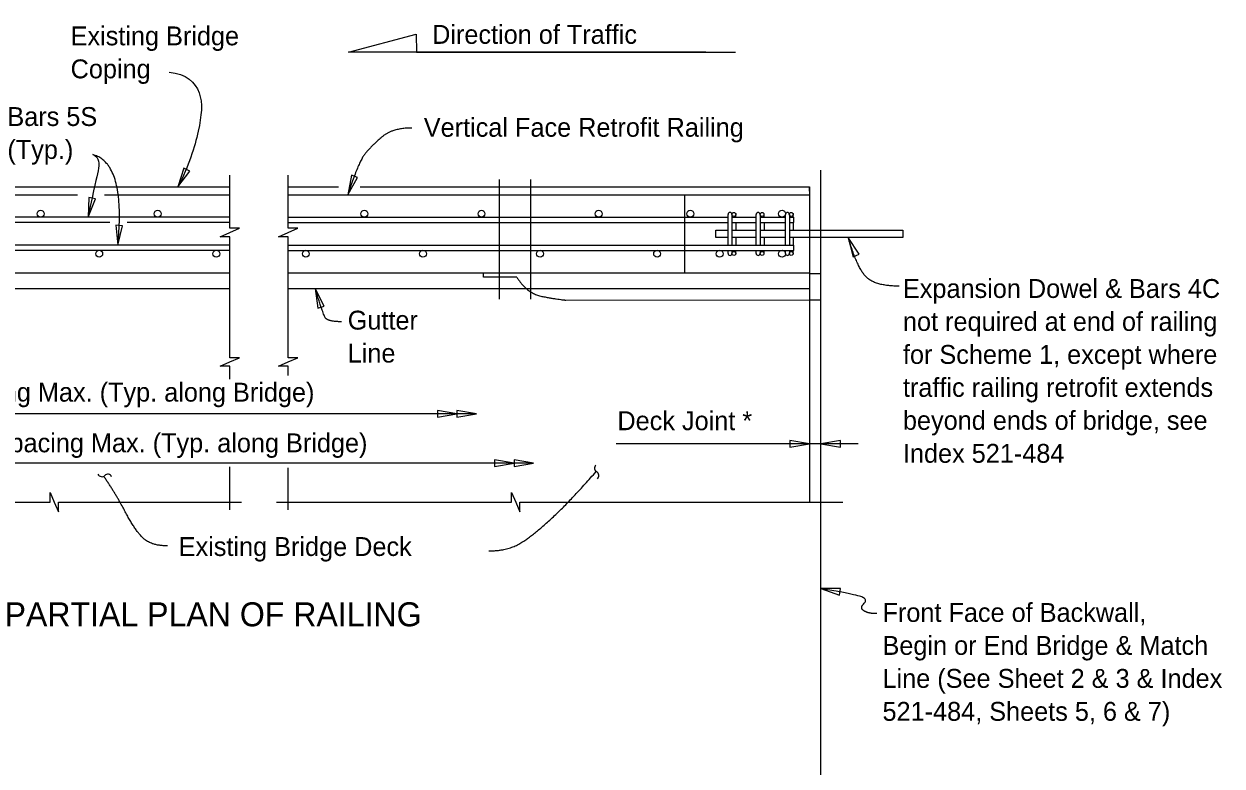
# Model space of a CAD drawing. Extents: x 0.1 to 40.1, y 0.1 to 25.4.
# Drawn here: x 6.61 to 19.4, y 17.39 to 25.31 of the extents above; entities that cross this region are included whole.
import ezdxf

# ---------------------------------------------------------------- set-up
doc = ezdxf.new("R2010")
doc.units = 0
for name, color, linetype in [('Dimension', 7, 'Continuous'), ('Miscellaneous', 7, 'Continuous'), ('Rebar', 7, 'Continuous'), ('TextStructures', 7, 'Continuous'), ('TrafBarrierConc', 7, 'Continuous')]:
    doc.layers.add(name, color=color, linetype=linetype)

msp = doc.modelspace()

# ---------------------------------------------------------------- linework, layer by layer
at = {"layer": 'Dimension'}
for p, q in [((10.079, 25.008), (10.801, 25.2)), ((10.801, 25.2), (10.803, 25.008)), ((13.892, 25.008), (10.079, 25.008)), ((10.803, 25.008), (14.016, 25.008)), ((14.016, 25.008), (14.209, 25.008)), ((15.121, 9.931), (15.121, 23.75)), ((11.687, 23.649), (11.687, 22.373)), ((12.021, 23.649), (12.021, 22.373)), ((11.444, 21.148), (3.78, 21.148)), ((15.518, 20.828), (12.934, 20.828)), ((12.054, 20.62), (3.78, 20.62))]:
    msp.add_line(p, q, dxfattribs=at)
for points in [[(8.257, 23.57), (8.385, 23.739), (8.322, 23.771)], [(10.071, 23.487), (10.175, 23.671), (10.109, 23.695)], [(7.299, 23.247), (7.376, 23.444), (7.306, 23.458)], [(7.616, 22.95), (7.666, 23.155), (7.596, 23.161)], [(15.412, 23.03), (15.466, 22.825), (15.53, 22.854)], [(9.723, 22.484), (9.751, 22.275), (9.818, 22.296)], [(11.236, 21.148), (11.027, 21.183), (11.027, 21.113)], [(11.444, 21.148), (11.236, 21.183), (11.236, 21.113)], [(14.998, 20.828), (14.79, 20.864), (14.79, 20.793)], [(15.121, 20.828), (15.329, 20.793), (15.329, 20.864)], [(11.846, 20.62), (11.638, 20.656), (11.638, 20.585)], [(12.054, 20.62), (11.846, 20.656), (11.846, 20.585)], [(15.119, 19.281), (15.319, 19.212), (15.33, 19.282)]]:
    msp.add_lwpolyline(points, close=True, dxfattribs=at)
for points in [[(8.81, 22.036), (8.81, 23.039), (8.707, 23.039), (8.81, 23.084), (8.913, 23.129), (8.81, 23.129), (8.81, 23.695)], [(9.435, 22.036), (9.435, 23.039), (9.332, 23.039), (9.435, 23.084), (9.539, 23.129), (9.435, 23.129), (9.435, 23.695)], [(8.81, 21.518), (8.81, 21.656), (8.707, 21.656), (8.81, 21.701), (8.913, 21.746), (8.81, 21.746), (8.81, 22.036)], [(9.435, 21.558), (9.435, 21.656), (9.332, 21.656), (9.435, 21.701), (9.539, 21.746), (9.435, 21.746), (9.435, 22.036)], [(8.81, 20.123), (8.81, 20.58)], [(9.435, 20.123), (9.435, 20.57)], [(5.406, 20.203), (6.892, 20.203), (6.892, 20.306), (6.937, 20.203), (6.982, 20.1), (6.982, 20.203), (8.935, 20.203)], [(9.31, 20.203), (11.818, 20.203), (11.818, 20.306), (11.863, 20.203), (11.908, 20.1), (11.908, 20.203), (15.357, 20.203)]]:
    msp.add_lwpolyline(points, dxfattribs=at)
for centre, start, end in [((12.748, 20.567), 131.172, 242.8992), ((7.445, 20.521), 203.672, 315.3992), ((7.509, 20.458), 23.672, 135.3992), ((12.707, 20.488), 311.172, 62.8992)]:
    msp.add_arc(centre, 0.0447, start, end, dxfattribs=at)
for points, degree in [([(8.164, 24.797), (8.346, 24.777), (8.538, 24.597), (8.497, 24.199), (8.374, 23.794), (8.257, 23.57)], 3), ([(10.753, 24.199), (10.548, 24.199), (10.33, 24.014), (10.187, 23.844), (10.071, 23.487)], 2), ([(7.35, 23.915), (7.422, 23.887), (7.415, 23.749), (7.365, 23.58), (7.299, 23.247)], 3), ([(7.616, 22.95), (7.704, 23.816), (7.35, 23.915)], 2), ([(15.956, 22.511), (15.729, 22.511), (15.521, 22.67), (15.412, 23.03)], 2), ([(10.004, 22.131), (9.852, 22.131), (9.803, 22.225), (9.723, 22.484)], 2), ([(8.145, 19.738), (7.963, 19.738), (7.79, 19.92), (7.603, 20.279), (7.466, 20.481)], 2), ([(11.575, 19.684), (11.782, 19.684), (12.058, 19.856), (12.442, 20.211), (12.722, 20.531)], 2), ([(15.72, 19.014), (15.625, 19.014), (15.535, 19.075), (15.619, 19.157), (15.535, 19.212), (15.119, 19.281)], 2)]:
    msp.add_open_spline(points, degree=degree, dxfattribs=at)
at = {"layer": 'Miscellaneous'}
for p, q in [((11.521, 22.608), (11.521, 22.653)), ((11.875, 22.608), (11.521, 22.608)), ((12.398, 22.362), (14.998, 22.363))]:
    msp.add_line(p, q, dxfattribs=at)
for centre, radius, start, end in [((14.959, 209.646), 187, 270.0111, 270.05053), ((14.959, 209.657), 187.291, 270.01108, 270.04964)]:
    msp.add_arc(centre, radius, start, end, dxfattribs=at)
msp.add_open_spline([(11.875, 22.608), (11.982, 22.431), (12.323, 22.368), (12.398, 22.362)], degree=2, dxfattribs=at)
at = {"layer": 'Rebar'}
for p, q in [((8.81, 23.247), (4.131, 23.247)), ((7.531, 23.19), (4.131, 23.19)), ((8.81, 23.19), (7.715, 23.19)), ((9.435, 23.247), (14.13, 23.247)), ((9.435, 23.19), (14.13, 23.19)), ((14.13, 22.95), (14.13, 23.277)), ((14.172, 23.277), (14.172, 22.95)), ((14.172, 23.247), (14.43, 23.247)), ((14.172, 23.19), (14.43, 23.19)), ((14.214, 23.247), (14.214, 23.277)), ((14.214, 23.19), (14.214, 23.108)), ((14.43, 22.95), (14.43, 23.277)), ((14.472, 23.277), (14.472, 22.95)), ((14.472, 23.247), (14.743, 23.247)), ((14.472, 23.19), (14.743, 23.19)), ((14.514, 23.247), (14.514, 23.277)), ((14.514, 23.19), (14.514, 23.108)), ((14.743, 22.95), (14.743, 23.277)), ((14.785, 23.277), (14.785, 23.217)), ((14.785, 23.247), (14.831, 23.247)), ((14.785, 23.217), (14.785, 22.95)), ((14.785, 23.19), (14.831, 23.19)), ((14.826, 23.247), (14.826, 23.277)), ((14.826, 23.19), (14.826, 23.108)), ((14.831, 23.19), (14.831, 23.247)), ((14.214, 23.03), (14.214, 22.95)), ((14.514, 23.03), (14.514, 22.95)), ((14.826, 23.03), (14.826, 22.95)), ((15.996, 23.108), (15.996, 23.03)), ((8.81, 22.95), (6.273, 22.95)), ((9.435, 22.95), (14.831, 22.95)), ((14.831, 22.893), (14.831, 22.95)), ((8.81, 22.893), (3.459, 22.893)), ((9.435, 22.893), (14.831, 22.893)), ((14.13, 22.86), (14.13, 22.893)), ((14.172, 22.893), (14.172, 22.86)), ((14.214, 22.86), (14.214, 22.893)), ((14.43, 22.86), (14.43, 22.893)), ((14.472, 22.893), (14.472, 22.86)), ((14.514, 22.86), (14.514, 22.893)), ((14.743, 22.86), (14.743, 22.893)), ((14.785, 22.893), (14.785, 22.86)), ((14.826, 22.86), (14.826, 22.893))]:
    msp.add_line(p, q, dxfattribs=at)
for points in [[(14.13, 23.03), (13.998, 23.03), (13.998, 23.108), (14.13, 23.108)], [(14.172, 23.108), (14.43, 23.108)], [(14.43, 23.03), (14.172, 23.03)], [(14.472, 23.108), (14.743, 23.108)], [(14.743, 23.03), (14.472, 23.03)], [(14.785, 23.108), (15.996, 23.108)], [(15.996, 23.03), (14.785, 23.03)]]:
    msp.add_lwpolyline(points, dxfattribs=at)
for centre, radius in [((6.792, 23.284), 0.0365), ((8.042, 23.284), 0.0365), ((10.248, 23.284), 0.0365), ((11.498, 23.284), 0.0365), ((12.748, 23.284), 0.0365), ((13.727, 23.284), 0.0365), ((14.193, 23.277), 0.0208), ((14.493, 23.277), 0.0208), ((14.706, 23.284), 0.0365), ((14.805, 23.277), 0.0208), ((7.417, 22.857), 0.0365), ((8.667, 22.857), 0.0365), ((9.623, 22.857), 0.0365), ((10.873, 22.857), 0.0365), ((12.123, 22.857), 0.0365), ((13.373, 22.857), 0.0365), ((14.04, 22.857), 0.0365), ((14.193, 22.86), 0.0208), ((14.493, 22.86), 0.0208), ((14.706, 22.857), 0.0365), ((14.805, 22.86), 0.0208)]:
    msp.add_circle(centre, radius, dxfattribs=at)
for centre, start, end in [((14.151, 23.277), 0, 180), ((14.451, 23.277), 0, 180), ((14.764, 23.277), 0, 180), ((14.151, 22.86), 180, 0), ((14.451, 22.86), 180, 0), ((14.764, 22.86), 180, 0)]:
    msp.add_arc(centre, 0.0208, start, end, dxfattribs=at)
at = {"layer": 'TrafBarrierConc'}
for p, q in [((1.337, 23.57), (8.81, 23.57)), ((9.435, 23.57), (9.972, 23.57)), ((10.204, 23.57), (14.998, 23.57)), ((14.998, 23.57), (14.998, 23.487)), ((14.998, 23.524), (14.998, 23.57)), ((14.998, 23.57), (14.998, 20.203)), ((5.793, 23.487), (7.186, 23.487)), ((7.475, 23.487), (8.81, 23.487)), ((9.435, 23.487), (14.998, 23.487)), ((13.665, 23.487), (13.665, 22.653)), ((14.998, 23.487), (14.998, 22.653)), ((3.293, 22.653), (8.81, 22.653)), ((9.435, 22.653), (14.998, 22.653)), ((1.337, 22.487), (8.81, 22.487)), ((9.435, 22.487), (14.998, 22.487))]:
    msp.add_line(p, q, dxfattribs=at)

# ---------------------------------------------------------------- texts
at = {"layer": 'Dimension'}
for s, p in [('Existing Bridge ', (7.112, 25.082)), ('Coping', (7.112, 24.73)), ('Bars 5S', (6.437, 24.221)), ('(Typ.)', (6.437, 23.869)), ('Expansion Dowel & Bars 4C ', (15.997, 22.385)), ('Gutter', (10.07, 22.047)), ('not required at end of railing ', (15.997, 22.033)), ('Line', (10.07, 21.695)), ('for Scheme 1, except where ', (15.997, 21.681)), ('traffic railing retrofit extends ', (15.997, 21.329)), ('beyond ends of bridge, see ', (15.997, 20.977)), ('Index 521-484', (15.997, 20.625)), ('Front Face of Backwall, ', (15.779, 18.926)), ('Begin or End Bridge & Match ', (15.779, 18.574)), ('Line (See Sheet 2 & 3 & Index ', (15.779, 18.222)), ('521-484, Sheets 5, 6 & 7)', (15.779, 17.87))]:
    msp.add_text(s, height=0.2016, dxfattribs=at).set_placement(p)
at = {"layer": 'TextStructures'}
msp.add_text('Direction of Traffic', height=0.2016, rotation=359.9998, dxfattribs=at).set_placement((10.971, 25.098))
for s, height, p in [('Vertical Face Retrofit Railing', 0.2016, (10.882, 24.106)), ('1\'-3" Spacing Max. (Typ. along Bridge)', 0.2016, (5.102, 21.278)), ('Deck Joint *', 0.2016, (12.949, 20.973)), ('1\'-3" Spacing Max. (Typ. along Bridge)', 0.2016, (5.668, 20.737)), ('Existing Bridge Deck', 0.2016, (8.266, 19.63)), ('PARTIAL PLAN OF RAILING', 0.256, (6.407, 18.879))]:
    msp.add_text(s, height=height, dxfattribs=at).set_placement(p)

doc.saveas('drawing.dxf')
